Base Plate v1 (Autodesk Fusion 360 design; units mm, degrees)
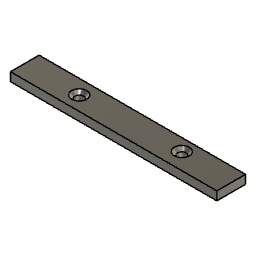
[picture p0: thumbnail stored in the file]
sketch "Sketch1" plane through (0, 0, 0) normal (0, 0, 1) x axis (1, 0, 0)
  line L1 (-72, 10) -> (72, 10)
  line L2 (-72, -10) -> (-72, 10)
  line L3 (72, -10) -> (-72, -10)
  line L4 (72, 10) -> (72, -10)
  line L5 (-72, -10) -> (72, 10)
  line L6 (72, -10) -> (-72, 10)
  point P6 (0, 0)
  point P1 (0, 0)
  point P4 (-72, -10)
  point P5 (72, -10)
  point P3 (-72, 10)
  horizontal L1
  perpendicular L1 L2
  parallel L1 L3
  parallel L2 L4
  coincident L5 P6
  coincident L6 P6
  coincident P1 P6
  dimension "d1" distance P4 P5 = 144
  dimension "d2" distance P3 P4 = 20
extrude "Extrude1" new body sketch "Sketch1" profile of L1 L2 L3 L4 along normal blind 6
sketch "Sketch2" plane through (0, 0, 0) normal (0, 1, 0) x axis (1, 0, 0)
  line L1 (-34, -6) -> (-34, 0)
  line L2 (-28.75, -6) -> (-34, -6)
  line L3 (-31, -3.75) -> (-28.75, -6)
  line L4 (-31, 0) -> (-31, -3.75)
  line L5 (-34, 0) -> (-31, 0)
  line L6 (72, 0) -> (-72, 0)
  line L7 (72, -6) -> (-72, -6)
  line L8 (-34, -17.0871) -> (-34, -6)
  point P6 (-31, 0)
  point P4 (-28.75, -6)
  point P7 (-72, 0)
  vertical L1
  perpendicular L1 L2
  perpendicular L2 L4
  perpendicular L1 L5
  coincident P6 L6
  coincident P4 L7
  perpendicular L2 L8
  dimension "d5" distance L1 P7 = 38
  dimension "d6" = 10.5
  dimension "d7" distance L1 L4 = 3
  dimension "d8" angle L3 L8 = 45
revolve "Revolve1" sketch "Sketch2" AlongAngle 360
hole "Hole1" sketch "Sketch2" HoleDepth 20 HoleDiameter 6 TipAngle 45 CSDiameter 10.5 CSAngle 90 RefDim1 108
